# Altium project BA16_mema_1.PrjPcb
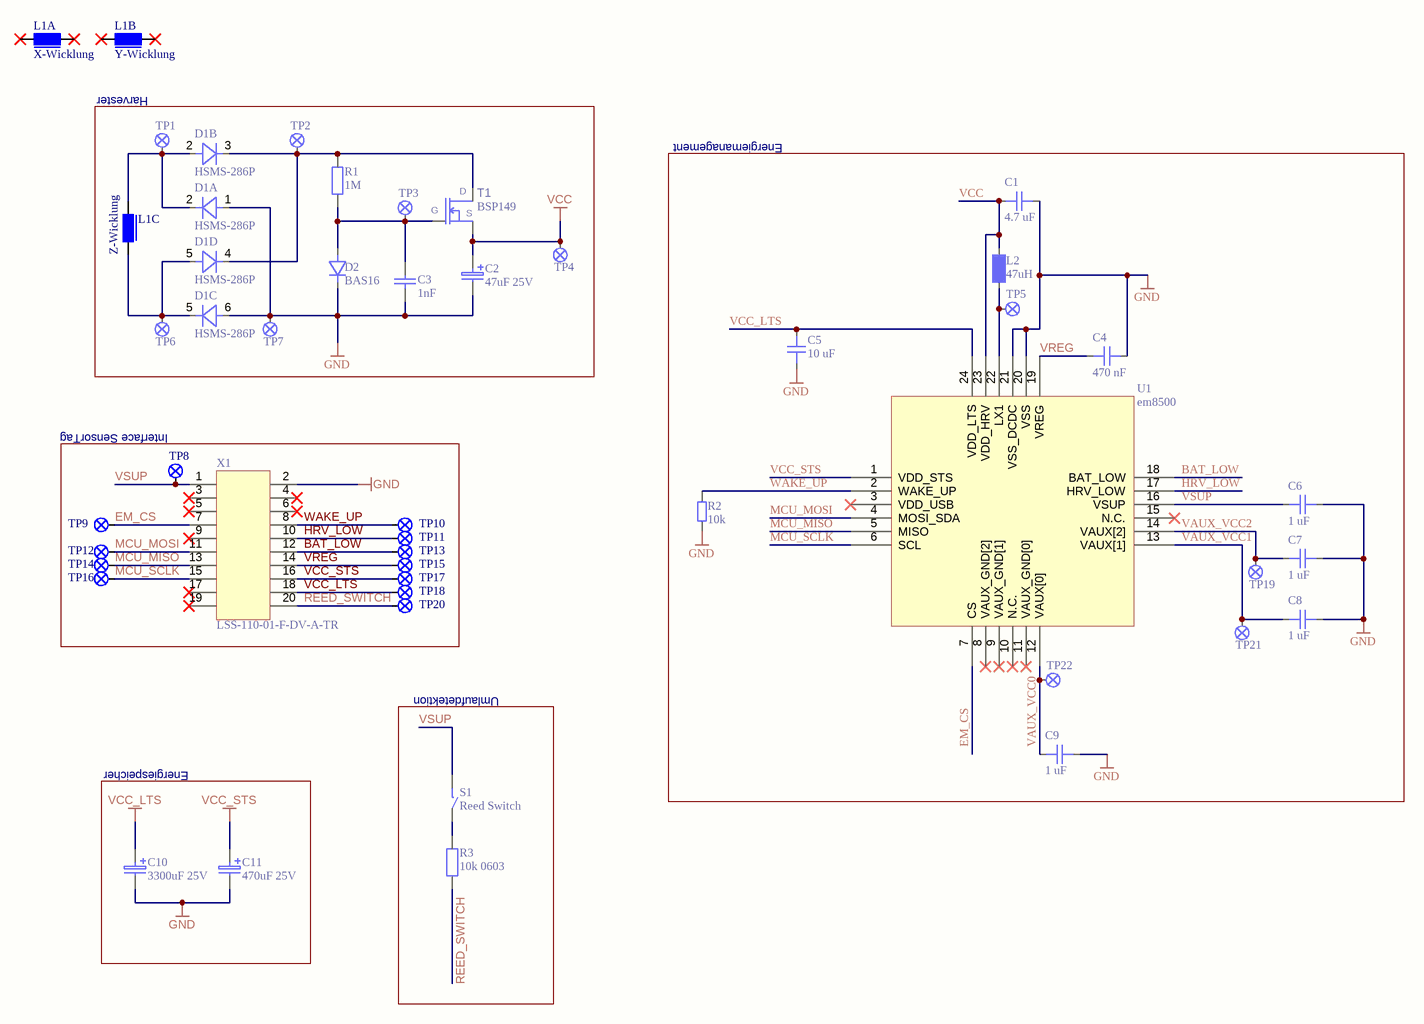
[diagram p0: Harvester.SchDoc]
1 sheet, 44 parts. Net scope: global (net labels, ports and power ports of the same name join across sheets).
Board file: BA16_mema_1_layout.PcbDoc

## Sheet Harvester.SchDoc
size A3

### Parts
C1  value 4.7 uF  [CHIP 1206]  (hidden comment: Cap)
C2  47uF 25V  [ELKO SMD-C 6.3x6.3]
C3  1nF  [CHIP 0603]
C4  value 470 nF  [CHIP 0603]  (hidden comment: Cap)
C5  value 10 uF  [CHIP 1206]  (hidden comment: Cap)
C6  value 1 uF  [CHIP 0603]  (hidden comment: Cap)
C7  value 1 uF  [CHIP 0603]  (hidden comment: Cap)
C8  value 1 uF  [CHIP 0603]  (hidden comment: Cap)
C9  value 1 uF  [CHIP 0603]  (hidden comment: Cap)
C10  3300uF 25V  [C_RAD_flex]
C11  470uF 25V  [C_RAD_flex]
D1  HSMS-286P  [SOT-363 (SC-70)]  (parts A,B,C,D of 4)
D2  BAS16  [SOT-23]
L1  X-Wicklung  [PREMO_3115N_0238J_2]  (parts A,B,C of 3)
L2  value 47uH  [CHIP 0805]  (hidden comment: L)
R1  1M  [CHIP 0603]
R2  value 10k  [CHIP 0603]  (hidden comment: R)
R3  10k 0603  [CHIP 0603]
S1  Reed Switch  [MK16-C-2]
T1  BSP149  [SOT-223]
TP1  TP_SMD  [TP SMD]  (value not drawn)  (no BOM)
TP2  TP_SMD  [TP SMD]  (value not drawn)  (no BOM)
TP3  TP_SMD  [TP SMD]  (value not drawn)  (no BOM)
TP4  TP_SMD  [TP SMD]  (value not drawn)  (no BOM)
TP5  TP_SMD  [TP SMD]  (value not drawn)  (no BOM)
TP6  TP_SMD  [TP SMD]  (value not drawn)  (no BOM)
TP7  TP_SMD  [TP SMD]  (value not drawn)  (no BOM)
TP8  TP_SMD  [TP SMD]  (value not drawn)  (no BOM)
TP9  TP_SMD  [TP SMD]  (value not drawn)  (no BOM)
TP10  TP_SMD  [TP SMD]  (value not drawn)  (no BOM)
TP11  TP_SMD  [TP SMD]  (value not drawn)  (no BOM)
TP12  TP_SMD  [TP SMD]  (value not drawn)  (no BOM)
TP13  TP_SMD  [TP SMD]  (value not drawn)  (no BOM)
TP14  TP_SMD  [TP SMD]  (value not drawn)  (no BOM)
TP15  TP_SMD  [TP SMD]  (value not drawn)  (no BOM)
TP16  TP_SMD  [TP SMD]  (value not drawn)  (no BOM)
TP17  TP_SMD  [TP SMD]  (value not drawn)  (no BOM)
TP18  TP_SMD  [TP SMD]  (value not drawn)  (no BOM)
TP19  TP_SMD  [TP SMD]  (value not drawn)  (no BOM)
TP20  TP_SMD  [TP SMD]  (value not drawn)  (no BOM)
TP21  TP_SMD  [TP SMD]  (value not drawn)  (no BOM)
TP22  TP_SMD  [TP SMD]  (value not drawn)  (no BOM)
U1  em8500  [QFN-24]
X1  LSS-110-01-F-DV-A-TR  [HEADER SMD 2x10 0.635mm]

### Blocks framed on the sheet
Harvester: C2 C3 D1 D2 L1 R1 T1 TP1-TP4 TP6 TP7
Energiemanagement: C1 C4-C9 L2 R2 TP5 TP19 TP21 TP22 U1
Interface SensorTag: TP8-TP18 TP20 X1
Umlaufdetektion: R3 S1
Energiespeicher: C10 C11

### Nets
GND: C1.2 C2.2(NEG) C3.1 C4.2 C5.2 C6.2 C7.2 C8.2 C9.2 C10.2(NEG) C11.2(NEG) D1.1(A) D1.6(A) D2.2(K) R2.2 TP7.1 U1.20(VSS) U1.21(VSS_DCDC) X1.2
VCC: C1.1 C2.1(POS) L2.2 T1.2(S) TP4.1 U1.23(VDD_HRV)
VCC_LTS: C5.1 C10.1(POS) TP18.1 U1.24(VDD_LTS) X1.18
VCC_STS: C11.1(POS) TP17.1 U1.1(VDD_STS) X1.16
BAT_LOW: TP13.1 U1.18(BAT_LOW) X1.12
EM_CS: TP9.1 U1.7(CS) X1.7
HRV_LOW: TP11.1 U1.17(HRV_LOW) X1.10
MCU_MISO: TP14.1 U1.5(MISO) X1.13
MCU_MOSI: TP12.1 U1.4(MOSI_SDA) X1.11
MCU_SCLK: TP16.1 U1.6(SCL) X1.15
REED_SWITCH: R3.1 TP20.1 X1.20
VAUX_VCC0: C9.1 TP22.1 U1.12(VAUX[0])
VAUX_VCC1: C8.1 TP21.1 U1.13(VAUX[1])
VAUX_VCC2: C7.1 TP19.1 U1.14(VAUX[2])
VREG: C4.1 TP15.1 U1.19(VREG) X1.14
VSUP: C6.1 S1.2 TP8.1 U1.16(VSUP) X1.1
WAKE_UP: R2.1 TP10.1 U1.2(WAKE_UP) X1.8
NetC3_2: C3.2 D2.1(A) R1.1 T1.1(G) TP3.1
NetD1_2: D1.2(K) L1.8 TP1.1
NetD1_3: D1.3(K) D1.4(K) R1.2 T1.3(D) TP2.1
NetD1_5: D1.5(K) L1.4 TP6.1
NetL2_1: L2.1 TP5.1 U1.22(LX1)
NetR3_2: R3.2 S1.1

Not connected (* = marked no-connect by the designer): L1 2* 3* 6* 7*; U1 3(VDD_USB)* 8(VAUX_GND[2])* 9(VAUX_GND[1])* 10(N.C.)* 11(VAUX_GND[0])* 15(N.C.)*; X1 3* 4* 5* 6* 9* 17* 19*

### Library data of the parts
C1 = C: Capacitor; Manufacturer Part Number: GRM31CR71E475KA88L; Manufacturer: Murata; Dist Order No: 1828835RL
C2 = C POL: Capasitor Polarisiert; Manufacturer: Vishay; Class: 63 Capacitor; Dist Order No: 1187015; Man Order No: MAL215375479E3
C3 = C 50V: Capacitor 50V; Manufacturer: AVX; Class: 63 Capacitor; Dist Order No: 2332585RL; Man Order No: 06033C102KAT2A
C4 = C: Capacitor; Manufacturer Part Number: CGA3E3X7R1E474K080AB; Manufacturer: TDK; Dist Order No: 2210923RL
C5 = C: Capacitor; Manufacturer Part Number: CGA5L1X7R1E106K160AC; Manufacturer: TDK; Dist Order No: 2211068RL
C6-C9 = C: Capacitor; Manufacturer Part Number: CGA3E1X7R1E105K080AC; Manufacturer: TDK; Dist Order No: 2346962RL
C10 = C POL: Capasitor Polarisiert; Manufacturer: Panasonic; Class: 63 Capacitor; Dist Order No: 2313351; Man Order No: EEUFR1E332B; Note: RM 2.5mm/5mm/7.5mm/10mm
C11 = C POL: Capasitor Polarisiert; Manufacturer: Panasonic; Class: 63 Capacitor; Dist Order No: 2313355; Man Order No: EEUFR1E471B
D1 = HSMS-286P: Diode Schottky Quadro; Class: 11 Diode
D2 = D: Diode; Manufacturer: ON SEMICONDUCTOR; Class: 11 Diode; Dist Order No: 9558659RL; Man Order No: BAS16LT1G
L1 = PREMO 3015 0238J 2: Inductor; Class: 65 Indctor
L2 = L: Ind; Manufacturer Part Number: 0805PS-473KLB; Manufacturer: Coilcraft; Dist Order No: 2286575RL
R1 = R: Resistor; Manufacturer: Vishay; Class: 61 Resistor; Dist Order No: 1469746RL; Man Order No: CRCW06031M00FKEA
R2 = R: Resistor; Manufacturer Part Number: CRCW06031K00FKEA; Manufacturer: Vishay; Dist Order No: 1469740RL
R3 = R: Resistor; Manufacturer: Vishay; Class: 61 Resistor; Dist Order No: 1469740RL; Man Order No: CRCW06031K00FKEA
S1 = SWITCH MICRO NO: Switch Micro Normal Open; Manufacturer: STANDEXMEDER; Class: 81 Switch; Dist Order No: 1079488
T1 = BSP149: MOSFET N-Kanal; Manufacturer: Infineon; Class: 22 FET; Dist Order No: 2480627RL; Man Order No: BSP149 H6906
TP1-TP22 = TP_SMD: Testpoint SMD
U1 = em8500: Manufacturer: EM Microelectronic
X1 = HDR 20 POL ABW: Header 100 mil 20 Pol; Manufacturer: Samtech; Class: 73 Connector 100 mil; Dist Order No: 2504990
